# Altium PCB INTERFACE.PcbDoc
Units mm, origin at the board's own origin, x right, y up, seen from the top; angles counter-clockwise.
Board outline 41 x 13 mm, 2 copper layers (TopLayer, BottomLayer); 33 components, 17 nets, 63 pads, 4 vias.
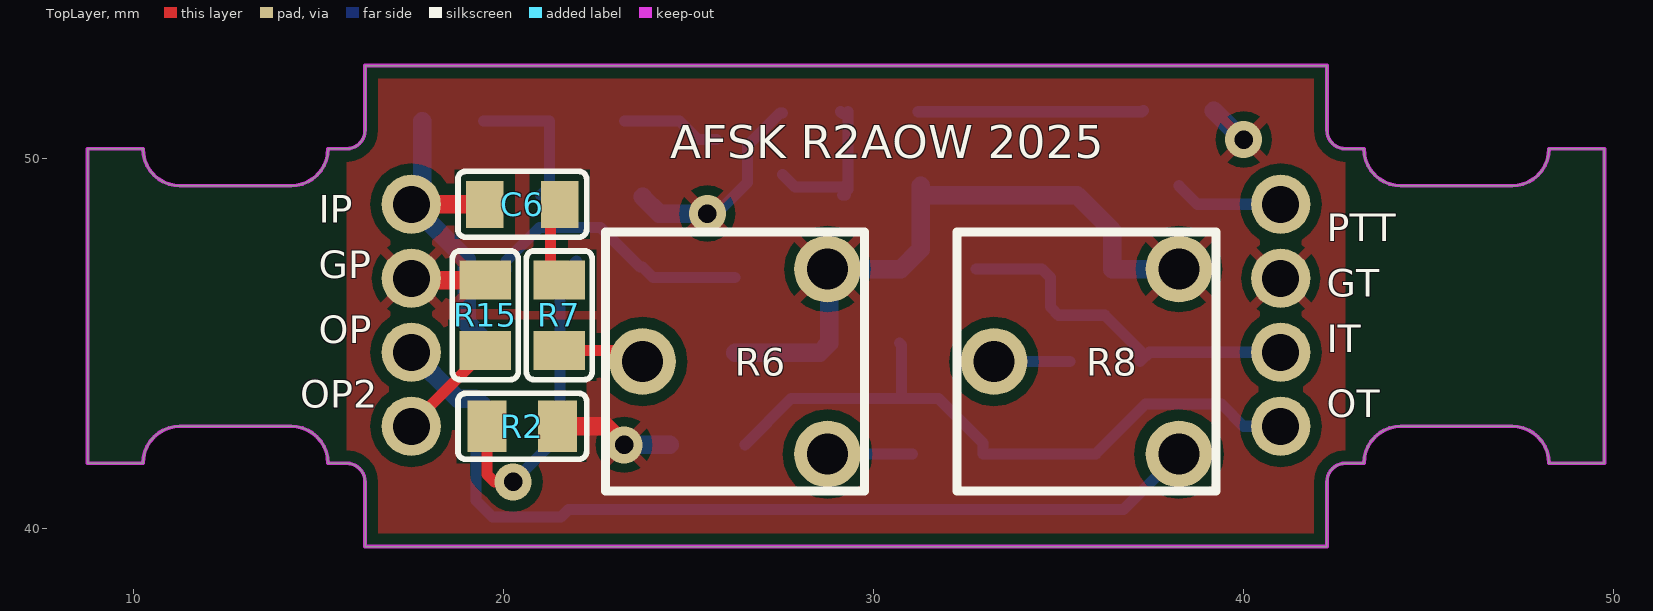
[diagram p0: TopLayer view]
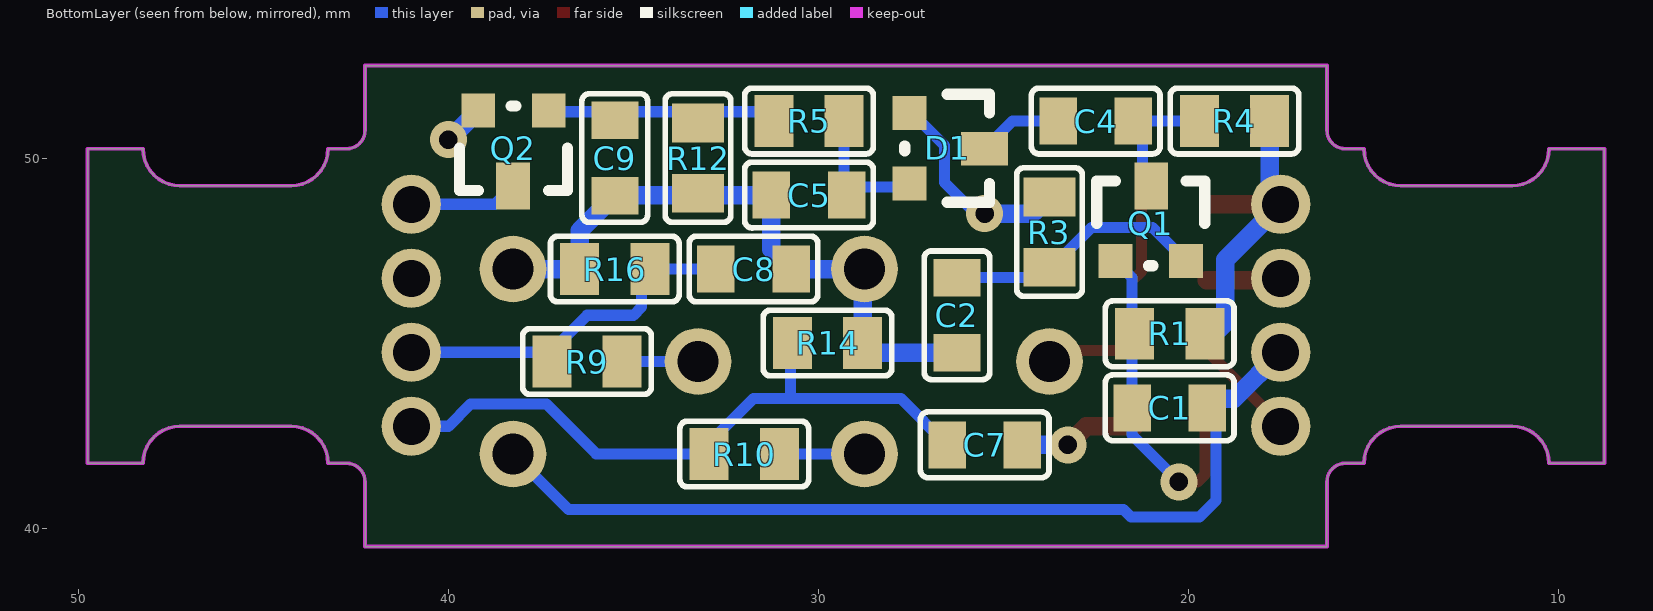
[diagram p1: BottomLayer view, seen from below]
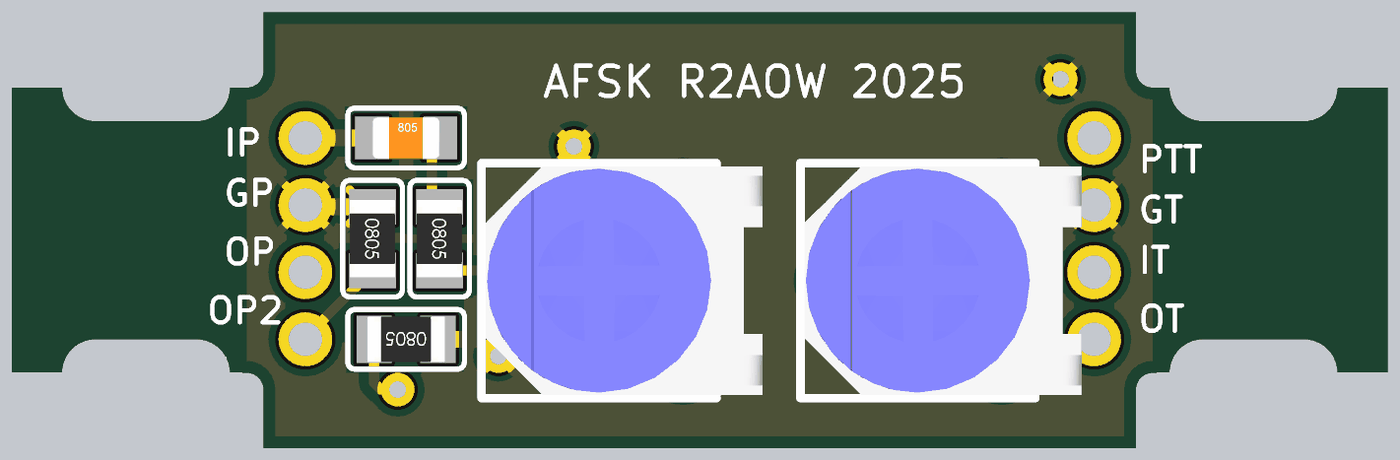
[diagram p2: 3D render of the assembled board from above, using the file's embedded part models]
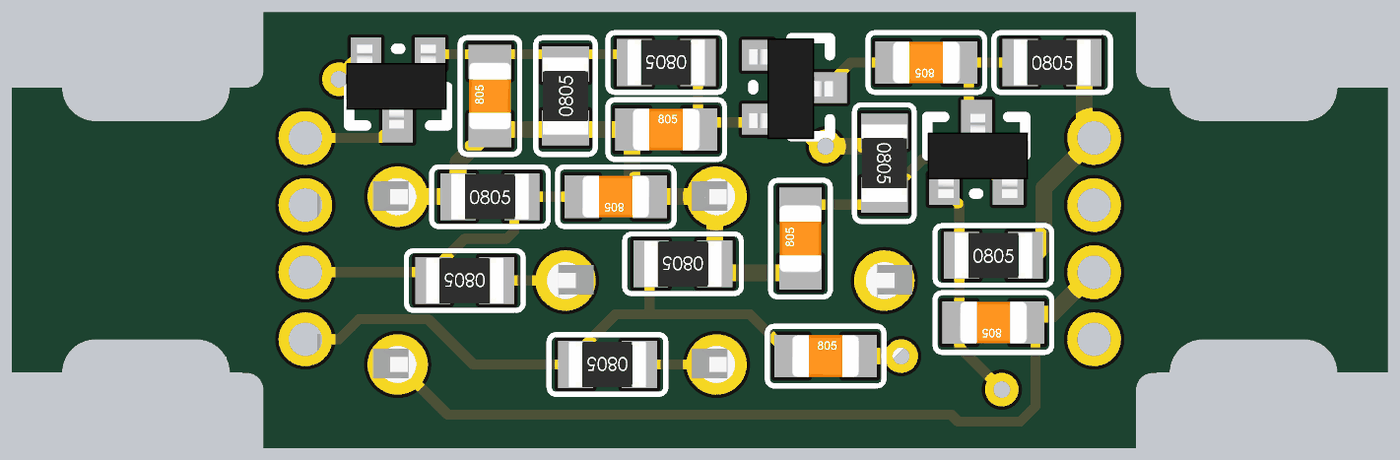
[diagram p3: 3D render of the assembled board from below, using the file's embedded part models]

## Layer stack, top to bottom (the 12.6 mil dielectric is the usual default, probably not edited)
TopSolder: solder mask 0.0102, Solder Resist, Dk 3.5
TopLayer: signal copper 0.0356
Dielectric1: core 0.32, FR-4, Dk 4.8
BottomLayer: signal copper 0.0356
BottomSolder: solder mask 0.0102, Solder Resist, Dk 3.5

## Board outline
8.75,41.75 10.25,41.75 cw(c11.25,41.75) 11.25,42.75 14.25,42.75 cw(c14.25,41.75) 15.25,41.75 15.75,41.75 cw(c15.75,41.25) 16.25,41.25 16.25,39.5 42.25,39.5 42.25,41.25 cw(c42.75,41.25) 42.75,41.75 43.25,41.75 cw(c44.25,41.75) 44.25,42.75 47.25,42.75 cw(c47.25,41.75) 48.25,41.75 49.75,41.75 49.75,50.25 48.25,50.25 cw(c47.25,50.25) 47.25,49.25 44.25,49.25 cw(c44.25,50.25) 43.25,50.25 42.75,50.25 cw(c42.75,50.75) 42.25,50.75 42.25,52.5 16.25,52.5 16.25,50.75 cw(c15.75,50.75) 15.75,50.25 15.25,50.25 cw(c14.25,50.25) 14.25,49.25 11.25,49.25 cw(c11.25,50.25) 10.25,50.25 8.75,50.25

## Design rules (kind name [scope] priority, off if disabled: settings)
Clearance Clearance_2 [All] p1: gap=0.3 ignorepadtopadclearanceinfootprint=FALSE except(0: Arc-Hole Track-Hole SMDPad-Hole THPad-Hole Via-Hole Fill-Hole Poly-Hole Region-Hole Text-Hole)
DiffPairsRouting [All] p1 off: maxlimit=0.254 minlimit=0.254 mostfreqgap=0.254 toplayer_minwidth=0.381 toplayer_maxwidth=0.381 toplayer_prefwidth=0.381 bottomlayer_minwidth=0.381 bottomlayer_maxwidth=0.381 bottomlayer_prefwidth=0.381 maxuncoupledlength=12.7
FabricationTestPointUsage TestPointUsage [All] p1: valid=0 allowmultiple=FALSE
FabricationTestpoint Testpoint [All] p1: side=3 testpointundercomponent=TRUE minsize=1.016 maxsize=2.54 preferedsize=1.524 minholesize=0.508 maxholesize=1.016 preferedholesize=0.813 testpointgrid=0.025 allowsidetop=TRUE allowsidebottom=TRUE usegrid=TRUE gridtolerance=0
Length [InNet('P_PCLK')] p1 off: maxlimit=7 minlimit=5
PlaneClearance [All] p1: clearance=0.254
PolygonConnect [All] p1: connectstyle=Relief reliefconductorwidth=0.254 reliefentries=4 polygonreliefangle="45 Angle" airgapwidth=0.254
RoutingVias [All] p1: holewidth=0.3 width=0.6 viastyle="Through Hole" minholewidth=0.3 minwidth=0.6 maxholewidth=1 maxwidth=1.5
SilkToSilkClearance [All] p1 off: silktosilkclearance=0.254
SilkToSolderMaskClearance SilkscreenOverComponentPads [IsPad] p1: minsilkscreentomaskgap=0.1 clearancetoexposedcopper=TRUE
SolderMaskExpansion [All] p1: expansion=0.102
Width Width_1 [All] p1: maxlimit=2 minlimit=0.3 preferedwidth=0.3
24 further rules are at their usual default settings.

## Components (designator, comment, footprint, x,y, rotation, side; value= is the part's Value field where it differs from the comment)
C1 "X7R-4.7UF-16V-20%-0805" C0805 20.5,43.25 r0 bottom value=4.7uF
C2 "X5R-10UF-16V-20%-0805" C0805 26.25,45.75 r90 bottom value=10uF
C4 "X7R-4.7UF-16V-20%-0805" C0805 22.5,51 r0 bottom value=4.7uF
C5 "X7R-4.7UF-16V-20%-0805" C0805 30.25,49 r180 bottom value=4.7uF
C6 "X7R-4.7UF-16V-20%-0805" C0805 20.5,48.75 r0 top value=4.7uF
C7 "NP0-1000PF-50V-5%-0805" C0805 25.5,42.25 r180 bottom value=1000pF
C8 "NP0-1000PF-50V-5%-0805" C0805 31.75,47 r0 bottom value=1000pF
C9 "NP0-1000PF-50V-5%-0805" C0805 35.5,50 r90 bottom value=1000pF
D1 "BAT54S215" SOT-23 27.532,51.215 r270 bottom
GP "PIN" PIN#1 17.5,45.25 r270 top
GT "PIN" PIN#2 41,45.5 r90 top
IP "PIN" PIN#3 17.5,48.75 r270 top
IT "PIN" PIN#2 41,43.5 r90 top
OP "PIN" PIN#1 17.5,43.25 r270 top
OP2 "PIN" PIN#3 17.5,42.75 r270 top
OT "PIN" PIN#2 41,41.5 r90 top
PTT "PIN" PIN#2 41,47.5 r90 top
Q1 "MMBT2222ALT1G" SOT-23 21.965,47.218 r180 bottom
Q2 "MMBT2222ALT1G" SOT-23 37.285,51.282 r0 bottom
R1 "33K-0.125W-5%-0805" R0805 20.5,45.25 r180 bottom value=33K
R2 "18K-0.125W-5%-0805" R0805 20.5,42.75 r180 top value=18K
R3 "120R-0.125W-5%-0805" R0805 23.75,48 r270 bottom value=120
R4 "3.3K-0.125W-5%-0805" R0805 18.75,51 r180 bottom value=3.3K
R5 "470R-0.125W-5%-0805" R0805 30.25,51 r0 bottom value=470
R6 "1k" 3306F 26.25,44.5 r90 top
R7 "1K-0.125W-5%-0805" R0805 21.5,45.75 r270 top value=1K
R8 "1k" 3306F 35.75,44.5 r90 top
R9 "1K-0.125W-5%-0805" R0805 36.25,44.5 r0 bottom value=1K
R10 "10K-0.125W-5%-0805" R0805 32,42 r0 bottom value=10K
R12 "12K-0.125W-5%-0805" R0805 33.25,50 r90 bottom value=12K
R14 "120R-0.125W-5%-0805" R0805 29.75,45 r0 bottom value=120
R15 "1K-0.125W-5%-0805" R0805 19.5,45.75 r270 top value=1K
R16 "120R-0.125W-5%-0805" R0805 35.5,47 r180 bottom value=120

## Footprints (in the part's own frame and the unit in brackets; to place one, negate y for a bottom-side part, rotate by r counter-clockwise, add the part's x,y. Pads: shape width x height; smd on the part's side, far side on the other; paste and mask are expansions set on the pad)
3306F [mm] "TRIMMER   Bourns Inc."
  round 1.8 hole 1.1: 1(-2.5,-2.5) 2(0,2.5) 3(2.5,-2.5)
  silkscreen extent -3.5,-3.5 3.5,3.5, body extent -3.4,-4.88 3.41,3.38, height 7.62
C0805 [mil]
  rect 40x50 smd: 1(-40,0) 2(40,0)
  silkscreen extent -68,-35 68,35, body extent -39,-25 39,25, height 31
PIN#1 [mm]
  round 1.6 hole 1: 1(-1.5,0)
PIN#2 [mm]
  round 1.6 hole 1: 1(1.25,0)
PIN#3 [mm]
  round 1.6 hole 1: 1(0,0)
R0805 [mm] "R0805"
  rect 1.05x1.4 smd: 1(-0.95,0) 2(0.95,0)
  silkscreen extent -1.74,-0.89 1.74,0.89, body extent -1.15,-0.67 1.15,0.67, height 0.76
SOT-23 [mil]
  rect 36x36 smd: 1(0,0) 2(75,0)
  rect 36x50 smd: 3(38,80)
  silkscreen extent -20,-5 95,85, body extent -20,-10 98,89, height 43

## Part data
C1 C4 C5 C6: library part "CAP X7R-4.7UF-16V-20%-0805", "CAP CER 4.7uF 16V 20% 0805"
C2: library part "CAP X5R-10UF-16V-20%-0805", "CAP CER 10uF 16V 20% 0805"
C7 C8 C9: library part "CAP NP0-1000PF-50V-5%-0805", "CAP CER 1000pF 50V 5% NP0 0805"
D1: library part BAT54S.215, "DIODE ARRAY GP 30V 200MA SOT23-3", Manufacturer="NXP Semiconductor"
GP GT IP IT OP OP2 OT PTT: "1 pin"
Q1 Q2: "NPN General-purpose Transistor", Manufacturer="ON Semiconductor"
R1: library part "RES 33K-0.125W-5%-0805", "RESISTOR 0805 1/8W 33K Ohm 5%"
R2: library part "RES 18K-0.125W-5%-0805", "RESISTOR 0805 1/8W 18K Ohm 5%"
R3 R14 R16: library part "RES 120R-0.125W-5%-0805", "RESISTOR 0805 1/8W 120 Ohm 5%"
R4: library part "RES 3.3K-0.125W-5%-0805", "RESISTOR 0805 1/8W 3.3K Ohm 5%"
R5: library part "RES 470R-0.125W-5%-0805", "RESISTOR 0805 1/8W 470 Ohm 5%"
R6 R8: library part 3306F-1-102, "Potentiometer", Manufacturer="Bourns Inc."
R7 R9 R15: library part "RES 1.0K-0.125W-5%-0805", "RESISTOR 0805 1/8W 1K Ohm 5%"
R10: library part "RES 10K-0.125W-5%-0805", "RESISTOR 0805 1/8W 10K Ohm 5%"
R12: library part "RES 12K-0.125W-5%-0805", "RESISTOR 0805 1/8W 12K Ohm 5%"

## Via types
v1: diameter 1, hole 0.5, TopLayer to BottomLayer, 4 vias

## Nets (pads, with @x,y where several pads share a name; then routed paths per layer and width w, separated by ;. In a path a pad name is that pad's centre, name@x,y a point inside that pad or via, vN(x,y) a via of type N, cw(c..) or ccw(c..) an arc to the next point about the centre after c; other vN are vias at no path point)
"Audio In Phone": C6.1 IP.1 R1.2 R4.2 | length 9.2
  TopLayer w0.5: IP.1@17.5,49.1 IP.1 C6.1@19.4,48.75
  BottomLayer w0.5: R4.2 17.8,49.05 IP.1 19,47.25 19,45.55 R1.2@19.55,45
"Audio In Radio": C8.2 IT.1 R9.2 R16.2 | length 10
  BottomLayer w0.3: C8.2 R16.2 34.775,46.775 34.775,45.975 35,45.75 36.25,45.75 37.2,44.8 R9.2 37.45,44.75 IT.1
"Audio Out Phone": C1.1 OP.1 R8.1 | length 25.1
  BottomLayer w0.3: C1.1 19.25,43.016 19.25,40.75 19.7,40.3 21.55,40.3 21.75,40.5 36.75,40.5 R8.1
  BottomLayer w0.5: OP.1 18.75,43.5 19.234,43.5 C1.1
"Audio Out Radio": C7.1 OT.1 R10.2 R14.2 | length 18.1
  BottomLayer w0.3: C7.1 27.766,43.5 30.75,43.5 ; R14.2 30.75,44.95 30.75,43.5 ; OT.1 40,42.75 39.4,43.35 37.35,43.35 36,42 R10.2 32.95,42.3 31.75,43.5 30.75,43.5
GND: C2.1 C5.1 C7.2 C8.1 C9.1 D1.1 GP.1 GT.1 Q2.2 R2.1 R3.1 R6.3 R8.3 R12.1 R14.1 R15.1 R16.1 | length 29.6
  TopLayer w0.5: GP.1 17.55,46.7 R15.1 ; R2.1 22.75,42.75 v1(23.25,42.25)
  BottomLayer w0.3: v1(25.5,48.5) 25.75,48.5 26.585,49.335 26.585,50.335 27.465,51.215 D1.1
  BottomLayer w0.5: v1(23.25,42.25) C7.2 ; R3.1 24.2,48.5 v1(25.5,48.5) ; C2.1 28.534,44.734 R14.1 28.8,46.95 R6.3 C8.1 31.266,47.532 C5.1 ; C5.1@31.266,49.25 C5.1 ; R8.3 R16.1 36.45,48.034 C9.1 35.484,49 C5.1 ; Q2.2 39.972,50.5 v1(40,50.5)
NetC1_2: C1.2 Q1.1 R1.1 R2.2 | length 8.8
  TopLayer w0.3: R2.2 19.55,41.45 19.75,41.25 v1(20.25,41.25)
  BottomLayer w0.3: v1(20.25,41.25) 21.516,42.516 C1.2 21.516,46.769 Q1.1
NetC2_2: C2.2 Q1.2 R3.2 | length 7.2
  BottomLayer w0.3: Q1.2@20.06,46.968 Q1.2@20.06,47.06 ; Q1.2 20.967,48.125 22.609,48.125 23.684,47.05 R3.2 24.034,46.766 C2.2
NetC4_1: C4.1 Q1.3 R4.1 | length 3.9
  BottomLayer w0.3: R4.1@19.45,51 R4.1 21.234,51 21.234,49.234 Q1.3@21,49
NetC4_2: C4.2 D1.3 | length 2.7
  BottomLayer w0.3: C4.2@23.266,51 24.75,51 25.25,50.5 D1.3@25.75,50.5
NetC5_2: C5.2 D1.2 R5.1 | length 4.3
  BottomLayer w0.3: D1.2@27.532,49.56 27.876,49.216 29.234,49.216 C5.2@29.234,49.25 ; R5.1@29.1,51.25 R5.1@29.15,51.2 ; C5.2@29.15,49 C5.2 ; C5.2@29.192,49.042 29.3,49.15 R5.1@29.3,51.25
NetC6_2: C6.2 R7.1 | length 2.1
  TopLayer w0.3: C6.2@21.266,48.75 21.266,46.934 R7.1
NetC9_2: C9.2 Q2.1 R5.2 R12.2 | length 6.1
  BottomLayer w0.3: R5.2@31.2,51.25 37.253,51.25 Q2.1
NetOP2_1: OP2.1 R15.2 | length 2.9
  TopLayer w0.3: OP2.1 17.5,42.8 R15.2
NetR6_1: R6.1 R10.1 | length 2.3
  BottomLayer w0.3: R6.1 R10.1
NetR6_2: R6.2 R7.2 | length 2.4
  TopLayer w0.3: R7.2 23.45,44.8 R6.2
NetR8_2: R8.2 R9.1 | length 2.4
  BottomLayer w0.3: R8.2@33.5,44.75 R8.2 R9.1
"PTT Radio": PTT.1 Q2.3 | length 3
  BottomLayer w0.3: Q2.3 38.75,48.75 PTT.1

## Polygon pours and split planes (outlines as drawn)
GND on TopLayer "GND" (solid, remove dead copper, pour order 0): 15.75,39.5 15.75,52.5 42.75,52.5 42.75,39.5

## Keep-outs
KeepOutLayer:
  the board outline again, w0.1

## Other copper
TopLayer:
  pour cut-out: 19,44 22.229,44 22.229,41.796 19,41.796

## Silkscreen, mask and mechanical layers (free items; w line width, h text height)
TopOverlay:
  text "AFSK R2AOW 2025" at 24.5,50 h0.9
Mechanical1:
  the board outline again, w0.1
